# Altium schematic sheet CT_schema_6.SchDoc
size 226 x 144 mm
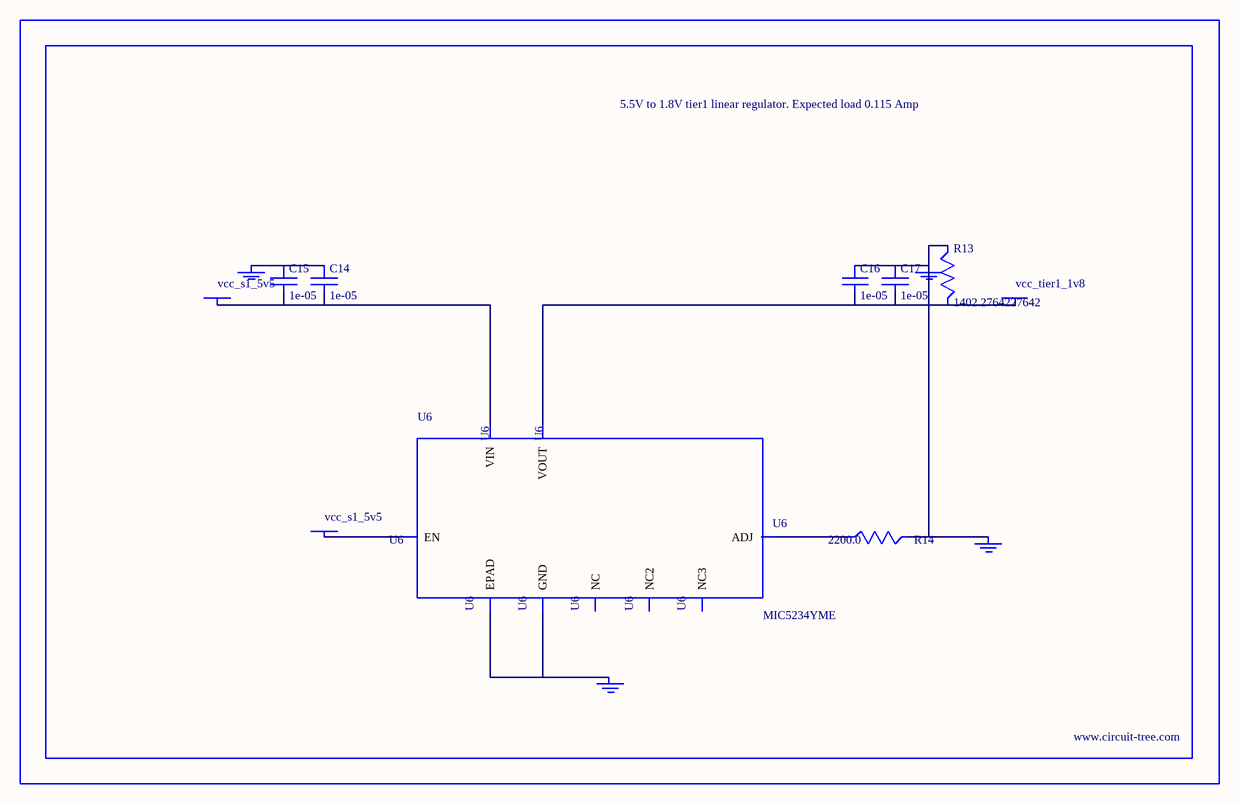
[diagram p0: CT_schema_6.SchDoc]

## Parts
BORDER5  (no value)
C14  1e-05  [C1210]
C15  1e-05  [C1210]
C16  1e-05  [C1210]
C17  1e-05  [C1210]
GND_INSTANCE_5_0  (no value)
GND_INSTANCE_5_1  (no value)
GND_INSTANCE_5_2  (no value)
GND_INSTANCE_5_3  (no value)
POWER_INSTANCE_5_0  vcc_tier1_1v8
POWER_INSTANCE_5_1  vcc_s1_5v5
POWER_INSTANCE_5_2  vcc_s1_5v5
R13  1402.2764227642  [R0603]
R14  2200.0  [R0603]
U6  MIC5234YME  [SOIC-8_EP]

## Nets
NetC14_1: C14.1 C15.1 GND_INSTANCE_5_3.0(GND)
NetC14_2: C14.2 C15.2 POWER_INSTANCE_5_2.0(PWR) U6.8(VIN)
NetC16_1: C16.1 C17.1 GND_INSTANCE_5_0.0(GND) GND_INSTANCE_5_1.0(GND) R13.1 R14.2
NetC16_2: C16.2 C17.2 POWER_INSTANCE_5_0.0(PWR) R13.2 U6.1(VOUT)
NetGND_INSTANCE_5_2_0: GND_INSTANCE_5_2.0(GND) U6.7(GND) U6.EPAD
NetPOWER_INSTANCE_5_1_0: POWER_INSTANCE_5_1.0(PWR) U6.5(EN)
NetR14_1: R14.1 U6.4(ADJ)

Not connected (* = marked no-connect by the designer): U6 2(NC) 3(NC2) 6(NC3)

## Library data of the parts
BORDER5 = BORDER_PAGE5
C14-C17 = C1210C106K5PACTU
GND_INSTANCE_5_0-GND_INSTANCE_5_3 = GND
POWER_INSTANCE_5_0-POWER_INSTANCE_5_2 = PWR
R13 = R13
R14 = RC0603JR-072K2L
